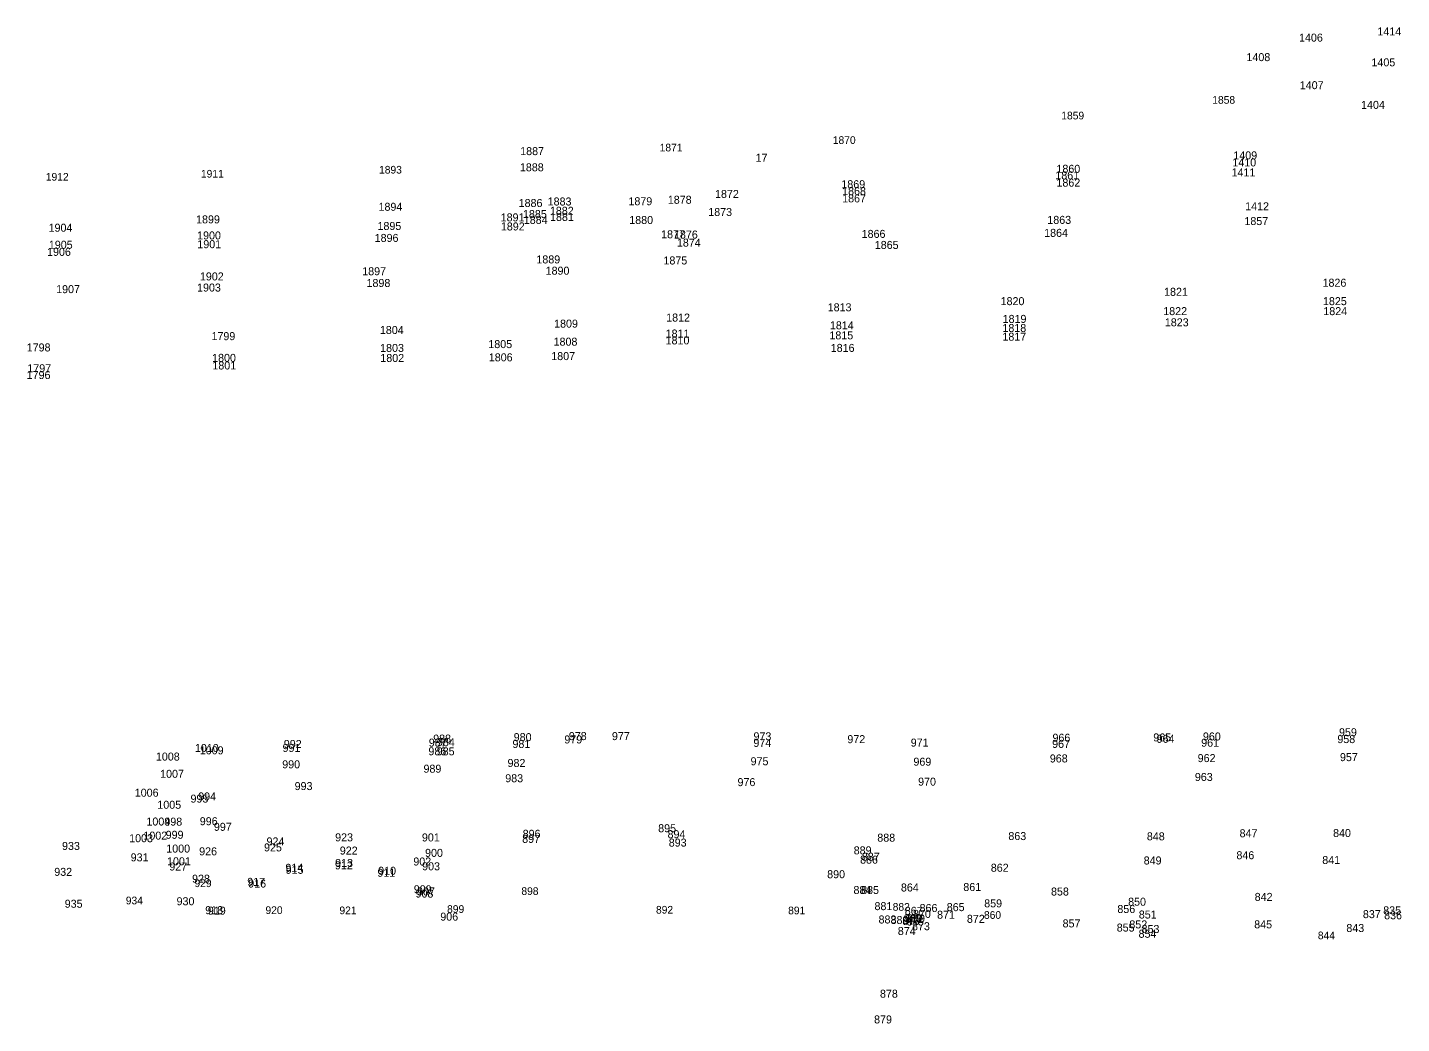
# Model space of a CAD drawing. Extents: x 359002 to 361405, y 1522603 to 1525369.
# Drawn here: x 359446.2 to 359875.7, y 1524585.2 to 1524896.6 of the extents above; entities that cross this region are included whole.
import ezdxf

# ---------------------------------------------------------------- set-up
doc = ezdxf.new("R2010")
doc.units = 0
for name, color, linetype in [('CBS_I', 7, 'Continuous'), ('DINV_I', 7, 'Continuous'), ('DS_I', 7, 'Continuous'), ('LABL_I', 7, 'Continuous'), ('LELB_I', 7, 'Continuous'), ('LELS_I', 7, 'Continuous'), ('LFNC_I', 7, 'Continuous'), ('LPST_I', 7, 'Continuous'), ('LS_I', 7, 'Continuous'), ('LSHC_I', 7, 'Continuous'), ('LUKL_I', 7, 'Continuous'), ('LUKP_I', 7, 'Continuous'), ('PE_I', 7, 'Continuous'), ('PRC_I', 7, 'Continuous'), ('RC_I', 7, 'Continuous'), ('RDP_I', 7, 'Continuous'), ('RDU_I', 7, 'Continuous'), ('RGW_I', 7, 'Continuous'), ('SDEL_I', 7, 'Continuous'), ('SRM_I', 7, 'Continuous'), ('ULP_I', 7, 'Continuous'), ('USMH_I', 7, 'Continuous'), ('UUPB_I', 7, 'Continuous')]:
    doc.layers.add(name, color=color, linetype=linetype)

msp = doc.modelspace()

# ---------------------------------------------------------------- texts
at = {"layer": 'CBS_I'}
msp.add_text('17', height=2.501, dxfattribs=at).set_placement((359673.76, 1524854.64))
at = {"layer": 'DINV_I'}
msp.add_text('877', height=2.501, dxfattribs=at).set_placement((359720.57, 1524616.69))
at = {"layer": 'DS_I'}
msp.add_text('878', height=2.501, dxfattribs=at).set_placement((359712.65, 1524593.28))
at = {"layer": 'LABL_I'}
for s, p in [('1409', (359823.1, 1524855.4)), ('1868', (359700.82, 1524844.23)), ('1884', (359601.32, 1524835.22)), ('1901', (359499.29, 1524827.63)), ('1826', (359850.98, 1524815.58)), ('1820', (359750.36, 1524809.82)), ('1821', (359801.45, 1524812.74)), ('1813', (359696.31, 1524807.9)), ('1804', (359556.34, 1524800.8)), ('1809', (359610.8, 1524802.79)), ('1812', (359645.83, 1524804.69)), ('1799', (359503.71, 1524798.88)), ('1798', (359445.96, 1524795.35)), ('983', (359595.53, 1524660.65)), ('976', (359668.12, 1524659.44)), ('970', (359724.57, 1524659.58)), ('963', (359811.07, 1524661.05)), ('1006', (359479.73, 1524656.13)), ('994', (359499.56, 1524654.97)), ('994', (359499.56, 1524654.97)), ('993', (359529.7, 1524658.2)), ('901', (359569.48, 1524642.14)), ('894', (359646.26, 1524643.15)), ('926', (359499.86, 1524637.79)), ('924', (359520.92, 1524640.9)), ('922', (359543.82, 1524638.04)), ('931', (359478.45, 1524635.91)), ('931', (359478.45, 1524635.91)), ('887', (359706.99, 1524636.11)), ('849', (359795.08, 1524634.94)), ('841', (359850.89, 1524635.08)), ('932', (359454.57, 1524631.38)), ('862', (359747.29, 1524632.67)), ('856', (359786.85, 1524619.77)), ('857', (359769.73, 1524615.26)), ('855', (359786.65, 1524613.96))]:
    msp.add_text(s, height=2.501, dxfattribs=at).set_placement(p)
at = {"layer": 'LELB_I'}
for s, p in [('1410', (359822.79, 1524853.2)), ('1409', (359823.1, 1524855.4)), ('1861', (359767.46, 1524849.15)), ('1860', (359767.81, 1524851.2)), ('1411', (359822.54, 1524850.08)), ('1869', (359700.58, 1524846.38)), ('1868', (359700.82, 1524844.23)), ('1862', (359767.81, 1524846.87)), ('1894', (359555.92, 1524839.33)), ('1886', (359599.72, 1524840.51)), ('1883', (359608.79, 1524840.98)), ('1879', (359634.03, 1524841.06)), ('1879', (359634.03, 1524841.06)), ('1878', (359646.34, 1524841.52)), ('1872', (359661.1, 1524843.34)), ('1872', (359661.1, 1524843.34)), ('1867', (359700.83, 1524841.95)), ('1412', (359826.8, 1524839.48)), ('1899', (359498.9, 1524835.39)), ('1891', (359594.1, 1524836.01)), ('1885', (359601.07, 1524837.06)), ('1884', (359601.32, 1524835.22)), ('1882', (359609.48, 1524838.07)), ('1881', (359609.53, 1524836.14)), ('1880', (359634.29, 1524835.19)), ('1873', (359658.98, 1524837.7)), ('1863', (359764.96, 1524835.23)), ('1904', (359452.8, 1524832.78)), ('1895', (359555.6, 1524833.32)), ('1892', (359594.16, 1524833.18)), ('1877', (359644.25, 1524830.73)), ('1876', (359648.27, 1524830.64)), ('1866', (359706.93, 1524830.85)), ('1864', (359763.97, 1524831.17)), ('1857', (359826.56, 1524834.86)), ('1905', (359452.88, 1524827.46)), ('1900', (359499.22, 1524830.37)), ('1901', (359499.29, 1524827.63)), ('1896', (359554.72, 1524829.59)), ('1874', (359649.18, 1524828.11)), ('1865', (359711.03, 1524827.4)), ('1906', (359452.32, 1524825.23)), ('1889', (359605.26, 1524822.87)), ('1875', (359644.98, 1524822.54)), ('1897', (359550.83, 1524819.17)), ('1890', (359608.15, 1524819.34)), ('1907', (359455.16, 1524813.57)), ('1907', (359455.16, 1524813.57)), ('1903', (359499.2, 1524814.07)), ('1902', (359500.09, 1524817.55)), ('1898', (359552.17, 1524815.5)), ('1825', (359851.11, 1524809.82)), ('1822', (359801.19, 1524806.7)), ('1824', (359851.23, 1524806.69)), ('1814', (359697, 1524802.25)), ('1818', (359750.92, 1524801.43)), ('1819', (359750.99, 1524804.27)), ('1823', (359801.69, 1524803.2)), ('1805', (359590.24, 1524796.39)), ('1808', (359610.64, 1524797.15)), ('1810', (359645.65, 1524797.55)), ('1811', (359645.66, 1524799.69)), ('1815', (359696.85, 1524799.13)), ('1800', (359503.91, 1524792.09)), ('1803', (359556.42, 1524795.19)), ('1802', (359556.49, 1524792.06)), ('1806', (359590.39, 1524792.25)), ('1807', (359609.91, 1524792.64)), ('1797', (359446.15, 1524788.84)), ('1801', (359503.99, 1524789.71)), ('1796', (359445.95, 1524786.72)), ('987', (359571.62, 1524671.78)), ('984', (359574.17, 1524671.92)), ('974', (359673.09, 1524671.71)), ('971', (359722.26, 1524671.79)), ('961', (359813.05, 1524671.76)), ('958', (359855.61, 1524672.89)), ('1008', (359486.34, 1524667.43)), ('991', (359525.93, 1524670.12)), ('981', (359597.78, 1524671.37)), ('967', (359766.46, 1524671.39)), ('990', (359525.82, 1524665)), ('989', (359569.98, 1524663.63)), ('982', (359596.25, 1524665.42)), ('975', (359672.21, 1524665.96)), ('969', (359723.11, 1524665.82)), ('968', (359765.74, 1524666.84)), ('962', (359811.95, 1524666.95)), ('957', (359856.42, 1524667.25)), ('1007', (359487.66, 1524662.03)), ('1005', (359486.79, 1524652.36)), ('1005', (359486.79, 1524652.36)), ('995', (359497.16, 1524654.28)), ('1004', (359483.38, 1524647.12)), ('1004', (359483.38, 1524647.12)), ('996', (359500.05, 1524647.21)), ('1003', (359477.98, 1524641.9)), ('1002', (359482.43, 1524642.71)), ('999', (359489.39, 1524642.98)), ('997', (359504.46, 1524645.47)), ('923', (359542.36, 1524642.17)), ('901', (359569.48, 1524642.14)), ('896', (359600.98, 1524643.28)), ('894', (359646.26, 1524643.15)), ('888', (359711.82, 1524642.07)), ('863', (359752.78, 1524642.57)), ('848', (359796.07, 1524642.49)), ('847', (359825.05, 1524643.45)), ('840', (359854.27, 1524643.52)), ('933', (359457, 1524639.48)), ('1000', (359489.58, 1524638.66)), ('926', (359499.86, 1524637.79)), ('924', (359520.92, 1524640.9)), ('931', (359478.45, 1524635.91)), ('927', (359490.53, 1524633.04)), ('849', (359795.08, 1524634.94)), ('846', (359824.06, 1524636.58)), ('841', (359850.89, 1524635.08)), ('864', (359719.2, 1524626.49)), ('861', (359738.7, 1524626.64)), ('858', (359766.11, 1524625.23)), ('858', (359766.11, 1524625.23)), ('881', (359710.94, 1524620.66)), ('865', (359733.52, 1524620.35)), ('859', (359745.23, 1524621.53)), ('842', (359829.77, 1524623.55)), ('883', (359712.21, 1524616.49)), ('868', (359720.11, 1524616.89)), ('867', (359720.39, 1524619.19)), ('869', (359721.15, 1524616.81)), ('870', (359722.97, 1524618.24)), ('866', (359725.03, 1524620.07)), ('871', (359730.5, 1524617.97)), ('872', (359739.82, 1524616.69)), ('851', (359793.55, 1524618.04)), ('835', (359869.95, 1524619.35)), ('874', (359718.23, 1524612.88)), ('873', (359722.67, 1524614.38)), ('852', (359790.6, 1524614.95))]:
    msp.add_text(s, height=2.501, dxfattribs=at).set_placement(p)
at = {"layer": 'LELS_I'}
for s, p in [('1858', (359816.51, 1524872.79)), ('1859', (359769.32, 1524867.9)), ('1871', (359643.79, 1524857.89)), ('1870', (359697.91, 1524860.23)), ('1912', (359451.93, 1524848.75)), ('1911', (359500.41, 1524849.71)), ('1893', (359556.08, 1524850.96)), ('929', (359498.39, 1524627.87)), ('898', (359600.57, 1524625.41)), ('934', (359476.93, 1524622.48)), ('882', (359716.63, 1524620.47)), ('920', (359520.58, 1524619.45)), ('921', (359543.7, 1524619.39)), ('899', (359577.35, 1524619.8)), ('892', (359642.64, 1524619.58)), ('891', (359683.95, 1524619.36)), ('876', (359719.65, 1524616.04)), ('860', (359745.15, 1524617.94)), ('875', (359721.02, 1524615.86)), ('844', (359849.51, 1524611.56))]:
    msp.add_text(s, height=2.4, dxfattribs=at).set_placement(p)
at = {"layer": 'LFNC_I'}
for s, p in [('1887', (359600.2, 1524856.73)), ('1888', (359600.11, 1524851.67)), ('886', (359706.43, 1524635.2)), ('885', (359706.76, 1524625.71))]:
    msp.add_text(s, height=2.501, dxfattribs=at).set_placement(p)
at = {"layer": 'LPST_I'}
for s, p in [('998', (359488.98, 1524647.08)), ('999', (359489.39, 1524642.98)), ('1000', (359489.58, 1524638.66)), ('1001', (359489.82, 1524634.69)), ('837', (359863.59, 1524618.16)), ('836', (359870.23, 1524617.8))]:
    msp.add_text(s, height=2.501, dxfattribs=at).set_placement(p)
at = {"layer": 'LS_I'}
for s, p in [('987', (359571.62, 1524671.78)), ('984', (359574.17, 1524671.92)), ('986', (359571.51, 1524669.08)), ('985', (359574.12, 1524669.07))]:
    msp.add_text(s, height=2.501, dxfattribs=at).set_placement(p)
at = {"layer": 'LSHC_I'}
for s, p in [('881', (359710.94, 1524620.66)), ('880', (359715.97, 1524616.33))]:
    msp.add_text(s, height=2.501, dxfattribs=at).set_placement(p)
at = {"layer": 'LUKL_I'}
for s, p in [('1877', (359644.25, 1524830.73)), ('1876', (359648.27, 1524830.64)), ('998', (359488.98, 1524647.08)), ('1001', (359489.82, 1524634.69)), ('837', (359863.59, 1524618.16)), ('836', (359870.23, 1524617.8))]:
    msp.add_text(s, height=2.501, dxfattribs=at).set_placement(p)
at = {"layer": 'LUKP_I'}
for s, p in [('1414', (359868.12, 1524894.14)), ('895', (359643.33, 1524645.02)), ('935', (359457.84, 1524621.41)), ('879', (359710.81, 1524585.24))]:
    msp.add_text(s, height=2.501, dxfattribs=at).set_placement(p)
at = {"layer": 'PE_I'}
for s, p in [('1408', (359827.2, 1524886.12)), ('1407', (359843.86, 1524877.35)), ('1404', (359863.02, 1524871.19))]:
    msp.add_text(s, height=2.501, dxfattribs=at).set_placement(p)
at = {"layer": 'PRC_I'}
for s, p in [('1406', (359843.63, 1524892.22)), ('1405', (359866.27, 1524884.49))]:
    msp.add_text(s, height=2.501, dxfattribs=at).set_placement(p)
at = {"layer": 'RC_I'}
for s, p in [('913', (359542.36, 1524634.16)), ('914', (359526.81, 1524632.64)), ('910', (359555.82, 1524631.72)), ('917', (359514.89, 1524628.26)), ('909', (359566.94, 1524625.93)), ('907', (359567.94, 1524625.25)), ('918', (359501.75, 1524619.4))]:
    msp.add_text(s, height=2.501, dxfattribs=at).set_placement(p)
at = {"layer": 'RDP_I'}
for s, p in [('912', (359542.29, 1524633.41)), ('915', (359526.91, 1524632.03)), ('911', (359555.58, 1524631.09)), ('916', (359515.19, 1524627.72)), ('908', (359567.5, 1524624.59)), ('919', (359502.58, 1524619.24)), ('906', (359575.23, 1524617.38)), ('854', (359793.47, 1524612.02)), ('853', (359794.41, 1524613.52)), ('845', (359829.62, 1524614.96)), ('843', (359858.42, 1524613.82))]:
    msp.add_text(s, height=2.501, dxfattribs=at).set_placement(p)
at = {"layer": 'RDU_I'}
for s, p in [('897', (359600.82, 1524641.69)), ('893', (359646.63, 1524640.53)), ('889', (359704.44, 1524638.1)), ('903', (359569.55, 1524633.12)), ('900', (359570.47, 1524637.32)), ('908', (359567.5, 1524624.59)), ('907', (359567.94, 1524625.25)), ('884', (359704.37, 1524625.71)), ('883', (359712.21, 1524616.49)), ('874', (359718.23, 1524612.88))]:
    msp.add_text(s, height=2.501, dxfattribs=at).set_placement(p)
at = {"layer": 'RGW_I'}
for s, p in [('1816', (359697.26, 1524795.2)), ('988', (359573.01, 1524673.05)), ('980', (359598.18, 1524673.51)), ('978', (359615.4, 1524673.83)), ('977', (359628.87, 1524673.82)), ('973', (359673.12, 1524673.76)), ('966', (359766.57, 1524673.32)), ('965', (359798.08, 1524673.42)), ('960', (359813.59, 1524673.71)), ('959', (359856.13, 1524675.03)), ('1010', (359498.53, 1524670.11)), ('992', (359526.32, 1524671.36))]:
    msp.add_text(s, height=2.501, dxfattribs=at).set_placement(p)
at = {"layer": 'SDEL_I'}
for s, p in [('1817', (359750.92, 1524798.71)), ('972', (359702.46, 1524672.87)), ('964', (359799.12, 1524672.98)), ('1009', (359500.06, 1524669.38))]:
    msp.add_text(s, height=2.501, dxfattribs=at).set_placement(p)
at = {"layer": 'SRM_I'}
for s, p in [('1807', (359609.91, 1524792.64)), ('979', (359614, 1524672.78))]:
    msp.add_text(s, height=2.501, dxfattribs=at).set_placement(p)
at = {"layer": 'ULP_I'}
for s, p in [('925', (359520.14, 1524639.03)), ('902', (359566.8, 1524634.62)), ('850', (359790.21, 1524622.04))]:
    msp.add_text(s, height=2.501, dxfattribs=at).set_placement(p)
at = {"layer": 'USMH_I'}
for s, p in [('928', (359497.64, 1524629.24)), ('890', (359696.15, 1524630.64))]:
    msp.add_text(s, height=2.501, dxfattribs=at).set_placement(p)
at = {"layer": 'UUPB_I'}
msp.add_text('930', height=2.501, dxfattribs=at).set_placement((359492.8, 1524622.19))

doc.saveas('drawing.dxf')
